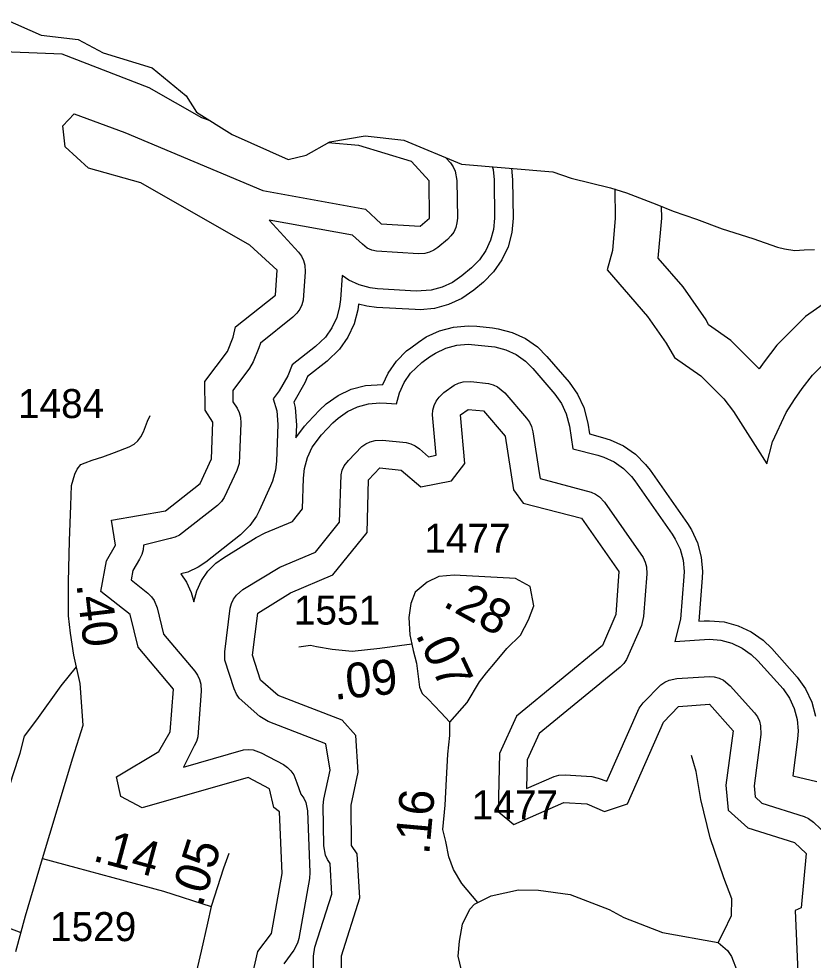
# Model space of a CAD drawing. Extents: x 2290615 to 2522933, y 819489 to 1012715.
# Drawn here: x 2339390 to 2342811, y 1000291 to 1004345 of the extents above; entities that cross this region are included whole.
import ezdxf

# ---------------------------------------------------------------- set-up
doc = ezdxf.new("R2010")
doc.units = 0
for name, color, linetype in [('Exist Boundary Political CountyLine', 7, 'Continuous'), ('Exist Hydrographic Buffer Line', 7, 'Continuous'), ('Exist Hydrographic Lake Shore', 7, 'Continuous'), ('Exist Road Non-System Type 51', 7, 'Continuous'), ('Exist Road Secondary Mileage Tenths English Label', 7, 'Continuous'), ('Exist Road Secondary Type 51 Attributed', 7, 'Continuous'), ('Exist Road Secondary Type 51 Number Label', 7, 'Continuous')]:
    doc.layers.add(name, color=color, linetype=linetype)

msp = doc.modelspace()

# ---------------------------------------------------------------- linework, layer by layer
at = {"layer": 'Exist Boundary Political CountyLine'}
msp.add_lwpolyline([(2339326.3, 1004344.5), (2339485.7, 1004274.3), (2339645.1, 1004255.2), (2339753.5, 1004197.8), (2339963.9, 1004134), (2340110.6, 1004012.7), (2340155.2, 1003942.5), (2340308.2, 1003846.8), (2340550.6, 1003738.4), (2340627.1, 1003757.5), (2340729.1, 1003814.9), (2340882.1, 1003840.4), (2341047.9, 1003821.3), (2341296.6, 1003719.2), (2341690.2, 1003686), (2341768.5, 1003659), (2341938.9, 1003616.8), (2342007.1, 1003595.6), (2342137.5, 1003545.2), (2342208, 1003516.3), (2342308.3, 1003481.3), (2342418.9, 1003440.6), (2342551.3, 1003398.5), (2342657.9, 1003361.5), (2342687.7, 1003353.9), (2342732, 1003346.5), (2342772, 1003349.1), (2342817.8, 1003351.7)], dxfattribs=at)
at = {"layer": 'Exist Hydrographic Buffer Line'}
for points in [[(2341227.3, 1003747.7), (2341248.8, 1003724.4), (2341260.9, 1003707.3), (2341269.7, 1003688.3), (2341276.9, 1003648.7), (2341278.9, 1003486.4), (2341277.1, 1003465.6), (2341271.6, 1003445.4), (2341263, 1003426.5), (2341250.9, 1003409.3), (2341236.1, 1003394.7), (2341195.1, 1003360), (2341177.9, 1003348), (2341158.8, 1003339.2), (2341138.7, 1003333.8), (2341111.2, 1003332.1), (2340930.2, 1003343.3), (2340909.9, 1003348.8), (2340890.8, 1003357.5), (2340869.5, 1003373.4), (2340827.2, 1003412.6), (2340468.8, 1003477.5), (2340594.9, 1003339.5), (2340606.8, 1003322.4), (2340615.6, 1003303.5), (2340621.1, 1003283.2), (2340622.6, 1003254.7)], [(2341429.3, 1003708), (2341432.5, 1003695.9), (2341436.8, 1003650.8), (2341438.9, 1003486.4), (2341434.6, 1003437.9), (2341421.9, 1003390.7), (2341401.4, 1003346.5), (2341373.5, 1003306.4), (2341339.2, 1003272.2), (2341297.8, 1003237.4), (2341257.8, 1003209.4), (2341213.5, 1003188.8), (2341166.4, 1003176.2), (2341102, 1003172.4), (2340934.9, 1003181.8), (2340902.5, 1003185.7), (2340855.1, 1003198.4), (2340810.8, 1003219), (2340781.9, 1003239.2), (2340775.3, 1003135.9), (2340771.6, 1003105.3), (2340758.9, 1003058.1), (2340738.4, 1003013.9), (2340710.3, 1002973.9), (2340668.3, 1002933.2), (2340566.8, 1002854), (2340547.9, 1002807.3), (2340511.6, 1002743.2), (2340485.2, 1002708.4), (2340501.6, 1002656.3), (2340505.7, 1002597), (2340499.7, 1002439.1), (2340495.6, 1002401.1), (2340482.9, 1002354), (2340474.3, 1002333.2), (2340425.3, 1002226.2)], [(2341512.3, 1003701), (2341516.8, 1003651.8), (2341518.9, 1003486.4), (2341513.3, 1003424), (2341497.1, 1003363.3), (2341470.7, 1003306.4), (2341434.6, 1003255), (2341390.7, 1003211.1), (2341349.5, 1003176.2)], [(2341957.4, 1003612.2), (2341958.9, 1003486.4), (2341946.6, 1003347.5), (2341924, 1003263.8), (2341997.4, 1003178.4), (2342097.7, 1003062.2), (2342177.7, 1002948), (2342214, 1002886.6), (2342328.2, 1002806.6), (2342426.6, 1002708.1), (2342468.9, 1002653.1), (2342611.2, 1002428.7), (2342636.2, 1002522.4), (2342695.2, 1002648.8), (2342731.1, 1002705.6), (2342764.1, 1002753.1), (2342808.2, 1002810.5), (2342906.6, 1002909)], [(2342579.2, 1002837.4), (2342456.6, 1002959.9), (2342360.6, 1003027), (2342351, 1003047.9), (2342250.9, 1003190.8), (2342143.7, 1003314.2), (2342158.8, 1003486.4), (2342158.3, 1003536.7)], [(2343389.7, 1003293.5), (2343247.2, 1003281.1), (2343078.9, 1003235.9), (2342920.8, 1003162.3), (2342778.1, 1003062.3), (2342654.8, 1002939.1), (2342599.9, 1002867.3), (2342579.2, 1002837.4)], [(2340622.6, 1003254.7), (2340614.2, 1003133), (2340608.6, 1003112.8), (2340599.8, 1003093.9), (2340587.9, 1003076.8), (2340569.9, 1003059.3), (2340430.2, 1002947.4), (2340424.1, 1002928), (2340399.7, 1002867.3), (2340384.1, 1002839.8), (2340311.1, 1002743.5), (2340311.7, 1002695.5), (2340330, 1002667.7), (2340338.6, 1002648.7), (2340344.1, 1002628.5), (2340346, 1002603.1), (2340338.2, 1002428.9), (2340328.9, 1002399.8), (2340274.8, 1002282.8), (2340262.9, 1002265.7), (2340245.5, 1002248.5), (2340081.9, 1002121.1), (2340063, 1002112.3), (2340041.9, 1002106.8), (2339926.8, 1002078.3), (2339925.2, 1002057.4), (2339919.7, 1002037.1), (2339910.2, 1002016.9), (2339881.1, 1001968.2), (2339873.9, 1001928.1), (2339946.1, 1001870.8), (2339960.9, 1001856), (2339973, 1001838.9), (2339985.5, 1001808.1), (2340013.6, 1001695.2), (2340147.9, 1001535.4), (2340160, 1001518.3), (2340168.6, 1001499.3), (2340174.1, 1001479.1), (2340175.8, 1001449.2), (2340160.2, 1001253), (2340154.6, 1001232.8), (2340145.6, 1001213.4), (2340098.7, 1001122.4), (2340357.2, 1001195.8), (2340377.9, 1001197.7), (2340398.7, 1001195.8), (2340434.1, 1001183.7), (2340529.9, 1001132.8), (2340547.1, 1001120.8), (2340561.9, 1001106)], [(2341349.5, 1003176.2), (2341297.8, 1003140.2), (2341241.2, 1003113.7), (2341180.3, 1003097.5), (2341118, 1003091.9), (2341097.5, 1003092.5), (2340930.4, 1003102), (2340888.3, 1003107), (2340853.5, 1003116.2), (2340850.4, 1003091.4), (2340834.2, 1003030.7), (2340807.7, 1002973.9), (2340771.6, 1002922.6), (2340717.7, 1002870.2), (2340632.8, 1002804.1), (2340622.2, 1002777.4), (2340574.2, 1002693.4), (2340580.3, 1002670.2), (2340585.7, 1002594), (2340583.6, 1002539.4), (2340620.1, 1002590.8), (2340635.7, 1002608.1), (2340684.7, 1002659.4), (2340713.4, 1002686.5), (2340764.9, 1002722.5), (2340821.7, 1002749.1), (2340882.4, 1002765.3), (2340957.6, 1002770.1), (2340980.2, 1002818.5), (2341016.1, 1002869.9), (2341060.4, 1002914.3), (2341078.4, 1002928.3), (2341111.4, 1002952.6), (2341144.8, 1002974.5), (2341201.6, 1003001.1), (2341262.3, 1003017.3), (2341324.9, 1003022.7), (2341362.6, 1003020.8), (2341429.7, 1003013.7), (2341454.5, 1003010.2), (2341515.2, 1002994), (2341572, 1002967.5), (2341623.4, 1002931.5), (2341664.4, 1002891), (2341760.6, 1002779.3), (2341796.7, 1002728), (2341823.2, 1002671.1), (2341840.6, 1002603.3), (2341848, 1002556.8), (2341904.4, 1002542.2), (2341937.2, 1002532), (2341994, 1002505.5), (2342045.4, 1002469.5), (2342089.7, 1002425.1), (2342108.6, 1002400.5), (2342269.8, 1002170.9), (2342286.6, 1002144.2), (2342313.2, 1002087.4), (2342329.4, 1002026.7), (2342335, 1001964.2), (2342333.9, 1001937), (2342319.4, 1001750.4), (2342341.5, 1001751.8), (2342364.9, 1001752.5), (2342427.4, 1001747.1), (2342488.1, 1001730.9), (2342544.9, 1001704.3), (2342596.4, 1001668.4), (2342633.1, 1001632.7), (2342742.6, 1001510), (2342778.7, 1001458.6), (2342805.1, 1001401.7), (2342821.3, 1001341.1)], [(2340425.3, 1002226.2), (2340413.4, 1002202.7), (2340385.3, 1002162.7), (2340344.3, 1002123), (2340195.5, 1002005.3), (2340161.8, 1001982.6), (2340117.7, 1001961.9), (2340087, 1001953.8), (2340111.4, 1001918.8), (2340131.9, 1001874.6), (2340143.2, 1001833.8), (2340155.9, 1001880.9), (2340176.4, 1001925.2), (2340204.5, 1001965.2), (2340238.9, 1001999.7), (2340270.9, 1002022.9), (2340412, 1002110.7), (2340451.4, 1002131.2), (2340568.4, 1002180.2), (2340612.3, 1002234.9), (2340615.8, 1002366.9), (2340620.1, 1002408.1), (2340632.8, 1002455.2), (2340653.3, 1002499.4), (2340693.3, 1002552.8), (2340742.3, 1002604.1), (2340764.9, 1002625.2), (2340804.9, 1002653.2), (2340849.2, 1002673.9), (2340896.3, 1002686.5), (2340944.9, 1002690.7), (2340973.2, 1002689.3), (2341016.1, 1002687.1), (2341029, 1002734.2), (2341049.5, 1002778.4), (2341077.4, 1002818.5), (2341126, 1002863.9), (2341159, 1002888.2), (2341184.8, 1002905.2), (2341229.1, 1002925.9), (2341276.5, 1002938.5), (2341324.9, 1002942.8), (2341354.2, 1002941.2), (2341440.3, 1002931.5), (2341487.7, 1002918.9), (2341532, 1002898.3), (2341572, 1002870.2), (2341604, 1002838.7), (2341699.3, 1002728), (2341727.4, 1002688), (2341747.9, 1002643.7), (2341761.6, 1002591), (2341776.8, 1002492.7), (2341884.5, 1002464.8), (2341909.7, 1002456.9), (2341954, 1002436.3), (2341994, 1002408.3), (2342028.4, 1002373.7), (2342043.2, 1002354.6), (2342204.1, 1002125), (2342217.5, 1002104.2), (2342238, 1002060), (2342250.7, 1002012.8), (2342255, 1001964.2), (2342254.2, 1001943), (2342240.2, 1001758.5), (2342215.6, 1001663.4), (2342364.9, 1001672.6), (2342413.5, 1001668.4), (2342460.7, 1001655.7), (2342505, 1001635), (2342544.9, 1001607), (2342573.6, 1001579.3), (2342681.5, 1001458.6), (2342709.4, 1001418.6), (2342729.9, 1001374.3), (2342742.6, 1001327.1), (2342746.9, 1001278.6), (2342744.5, 1001241.8), (2342723.7, 1001084.7), (2342826.7, 1001060.2)], [(2340738, 1000574.4), (2340730.2, 1000707.6), (2340718.9, 1000724.2), (2340710.1, 1000743.1), (2340703, 1000782.8), (2340700.9, 1000956.5), (2340703.8, 1000983.4), (2340731.3, 1001109.6), (2340712.4, 1001222.8), (2340463.7, 1001318.9), (2340428.4, 1001340.2), (2340339, 1001419.5), (2340326.9, 1001436.6), (2340316.8, 1001459.4), (2340277.7, 1001582.8), (2340276.9, 1001618.7), (2340300.6, 1001805.9), (2340306.2, 1001826.2), (2340315, 1001845.2), (2340326.9, 1001862.3), (2340355.4, 1001887), (2340513.5, 1001983.5), (2340667.7, 1002048.3), (2340770.8, 1002176.5), (2340777.6, 1002380.3), (2340783.1, 1002400.5), (2340791.9, 1002419.5), (2340809.2, 1002442.3), (2340867.6, 1002502.7), (2340884.8, 1002514.7), (2340903.9, 1002523.5), (2340924.2, 1002529), (2340956.8, 1002530.1), (2341057.7, 1002519.6), (2341078, 1002514.2), (2341096.9, 1002505.4), (2341115.1, 1002492.5), (2341155.1, 1002458), (2341187.1, 1002464.9), (2341171.9, 1002638.5), (2341173.5, 1002659.3), (2341179.1, 1002679.5), (2341187.9, 1002698.4), (2341199.8, 1002715.6), (2341220.7, 1002735), (2341264.8, 1002766.7), (2341283.9, 1002775.5), (2341304.2, 1002781), (2341337.4, 1002782.1), (2341412.6, 1002773.9), (2341432.9, 1002768.5), (2341451.8, 1002759.6), (2341482.6, 1002734.1), (2341576.9, 1002625.1), (2341589, 1002608), (2341597.6, 1002589), (2341603.3, 1002566.4), (2341630.8, 1002389.2), (2341634.9, 1002364.4), (2341854.9, 1002306.5), (2341874, 1002297.7), (2341891.2, 1002285.7), (2341912.1, 1002262.6), (2342078.9, 1002024.2), (2342087.7, 1002005.3), (2342093.2, 1001985.1), (2342094.6, 1001955.1), (2342080.7, 1001770.7), (2342071.5, 1001732.6), (2342007.9, 1001585.9), (2341996, 1001568.8), (2341980, 1001553.1), (2341630.6, 1001266.8), (2341579.3, 1001153.9), (2341576.5, 1001030), (2341696, 1001082.2), (2341716.1, 1001087.6), (2341743.6, 1001089.3), (2341857.6, 1001081.9), (2341884.7, 1001073.8), (2341923.2, 1001061), (2342061.8, 1001375.4), (2342079.5, 1001398.7), (2342154.7, 1001475.8), (2342171.9, 1001487.8), (2342191, 1001496.6), (2342224.2, 1001503.6), (2342364.9, 1001512.6), (2342385.6, 1001510.8), (2342405.9, 1001505.3), (2342425, 1001496.5), (2342454.5, 1001472.5), (2342558.9, 1001355.6), (2342571, 1001338.5), (2342579.6, 1001319.7), (2342585.1, 1001299.4), (2342585.9, 1001262.9), (2342556.6, 1001041.9), (2342561.1, 1000994.1), (2342590.9, 1000967.5)], [(2340561.9, 1001106), (2340574, 1001088.9), (2340587.1, 1001054.8), (2340604.9, 1001005.9), (2340616.8, 1000988.8), (2340625.7, 1000969.9), (2340633, 1000933.8), (2340643.9, 1000668.3), (2340642.3, 1000642.4), (2340596.1, 1000384.3), (2340590.8, 1000364.3), (2340574.2, 1000333.7), (2340530.9, 1000275.6)], [(2342590.9, 1000967.5), (2342771.9, 1000909.9), (2342791, 1000901), (2342813.1, 1000884.3), (2342873, 1000827), (2342884.9, 1000809.9), (2342893.7, 1000790.9), (2342911.2, 1000768)], [(2340535.4, 999640), (2340585.9, 999676), (2340604.9, 999684.8), (2340642.9, 999692), (2340755.2, 999694.6), (2340773.7, 999849.2), (2340784.2, 999885.4), (2340848.7, 1000038.8), (2340793.2, 1000048.3), (2340772.9, 1000053.8), (2340754, 1000062.6), (2340732.5, 1000078.4), (2340688, 1000120.8), (2340675.9, 1000137.9), (2340667.3, 1000156.8), (2340659.9, 1000196.8), (2340658.9, 1000308.4), (2340664.6, 1000346.2), (2340738, 1000574.4)]]:
    msp.add_lwpolyline(points, dxfattribs=at)
at = {"layer": 'Exist Hydrographic Lake Shore'}
for points in [[(2340211.6, 1003907.3), (2340178.8, 1003918.8), (2339951.8, 1004047.3), (2339575.8, 1004192.8), (2339250.8, 1004205.5), (2338975.8, 1004167.9), (2338868.8, 1004068.3), (2338861.8, 1003933.5), (2338971.9, 1003852.7), (2338963.9, 1003770.2), (2338898.9, 1003691.9), (2338915.9, 1003627.2), (2339007.8, 1003561.9), (2339009.8, 1003453.6), (2339118.9, 1003405.7), (2339120, 1003244.9), (2339254.9, 1003132.2), (2339229.9, 1002947.5)], [(2340312.9, 1002972.9), (2340322.8, 1003018.7), (2340495.9, 1003153.9), (2340502.8, 1003262.4), (2340384.9, 1003369.3), (2339916, 1003638.8), (2339689.8, 1003701.7), (2339588.9, 1003792.7), (2339578.9, 1003884.2), (2339628.9, 1003935.4), (2339845.8, 1003855.7), (2340440.9, 1003604.6), (2340882.8, 1003524.4), (2340950.9, 1003461.4), (2341118, 1003452), (2341158.8, 1003486.4), (2341156.9, 1003647.3), (2341080.9, 1003729.4), (2340854.9, 1003798.9), (2340720.9, 1003810.3)], [(2340396, 1000228.2), (2340420, 1000327.6), (2340478, 1000405.4), (2340523.9, 1000663.4), (2340512.9, 1000928.8), (2340487.9, 1000947.5), (2340470, 1001028.9), (2340377.9, 1001077.7), (2339920.9, 1000947.2), (2339829, 1000995.9), (2339811, 1001080.4), (2339992.9, 1001189.8), (2340041.9, 1001273.8), (2340056, 1001458.3), (2339903.9, 1001639.1), (2339869, 1001778.9), (2339742.9, 1001878.6), (2339766.9, 1002010.9), (2339806.9, 1002078.3), (2339788.8, 1002185.9), (2340022, 1002225.1), (2340170.8, 1002342.8), (2340219.9, 1002449.7), (2340225.8, 1002607.7), (2340192, 1002658.8), (2340190.9, 1002783.4), (2340288.3, 1002912.3), (2340312.9, 1002972.9)], [(2340779.8, 1000197.9), (2340779, 1000309.6), (2340859, 1000559), (2340847.9, 1000749), (2340822.9, 1000784.2), (2340820.9, 1000958), (2340852, 1001100.5), (2340842, 1001257.6), (2340782.9, 1001324.2), (2340506.9, 1001430.9), (2340430.9, 1001496.7), (2340396, 1001603.7), (2340419, 1001785.1), (2340559.8, 1001872.9), (2340741.9, 1001949.4), (2340890, 1002132.8), (2340895.9, 1002359.5), (2340944.9, 1002410.7), (2341037, 1002401.4), (2341120.9, 1002329.3), (2341253.9, 1002354.6), (2341310.9, 1002429.2), (2341291.9, 1002638.5), (2341324.9, 1002662.8), (2341391.9, 1002655.7), (2341484.8, 1002547.9), (2341520.9, 1002316.4), (2341562.9, 1002258.9), (2341813.9, 1002193.8), (2341974.9, 1001964.2), (2341960.9, 1001779.7), (2341903.9, 1001645.9), (2341533, 1001341.9), (2341460, 1001181.3), (2341453.9, 1000931.6), (2341521.9, 1000875.2), (2341737, 1000969.4), (2341836.9, 1000963.8), (2341913, 1000930.8), (2342012, 1000964.4), (2342166, 1001315.5), (2342232, 1001383.8), (2342364.9, 1001392.6), (2342467, 1001278.6), (2342435.8, 1001044.3), (2342445.9, 1000936.2), (2342530, 1000861), (2342730.9, 1000797.1), (2342781, 1000749.9), (2342759, 1000516), (2342734, 1000505.1), (2342745.9, 1000239.7)]]:
    msp.add_lwpolyline(points, dxfattribs=at)
at = {"layer": 'Exist Road Non-System Type 51'}
for points in [[(2339252.6, 1000464), (2339217.9, 1000503.4), (2339214.8, 1000539), (2339219.5, 1000582.4), (2339228.8, 1000627.4), (2339250.5, 1000689.4), (2339310.9, 1000900.3), (2339329.5, 1000973.2), (2339363.6, 1001086.4), (2339395.8, 1001182.6), (2339414.4, 1001255.5), (2339467.1, 1001325.3), (2339572.5, 1001472.6), (2339638.1, 1001553.3)], [(2342402.5, 1000366.2), (2342426.8, 1000413.6), (2342459.4, 1000483.4), (2342460.9, 1000554.7), (2342426.8, 1000644.6), (2342367.9, 1000816.8), (2342327.6, 1000982.7), (2342307.5, 1001103.6), (2342287.3, 1001171.9)], [(2339399.3, 1000408), (2339252.6, 1000464), (2339193, 1000482.6), (2339120.9, 1000505.1), (2339039.5, 1000533), (2338953, 1000546.5), (2338867, 1000555.6), (2338796.9, 1000566.7), (2338752.7, 1000580.1), (2338712.5, 1000593.7), (2338692.3, 1000613.5)]]:
    msp.add_lwpolyline(points, dxfattribs=at)
at = {"layer": 'Exist Road Secondary Type 51 Attributed'}
for points in [[(2339492.3, 1000729), (2339622.1, 1001162.1), (2339667, 1001303.2), (2339654.5, 1001482.1), (2339626.2, 1001604.5), (2339612.9, 1001698.4), (2339604, 1001774.2), (2339604.4, 1001920.1), (2339608.2, 1002096.2), (2339614.3, 1002248.1), (2339617.4, 1002334.3), (2339630.7, 1002384.3), (2339640.5, 1002404.5), (2339656.3, 1002424.6), (2339676.1, 1002433), (2339705.9, 1002443.2), (2339751.8, 1002457.7), (2339801.6, 1002476.4), (2339865.2, 1002501.2), (2339887.1, 1002513.5), (2339903, 1002527.6), (2339914.7, 1002543.7), (2339926.4, 1002566), (2339943.9, 1002612.1), (2339955.7, 1002636.2)], [(2341592.2, 1001899.2), (2341528.7, 1001934.3), (2341265.3, 1001948.3), (2341198.6, 1001943.6), (2341149.1, 1001918.8), (2341096.4, 1001875.4), (2341077.8, 1001827.3), (2341070, 1001766.8), (2341074.7, 1001692.4), (2341083, 1001651.6)], [(2341246.7, 1001315.6), (2341321.1, 1001400.9), (2341373.8, 1001489.2), (2341404.7, 1001528), (2341443.5, 1001574.5), (2341491.5, 1001633.5), (2341550.4, 1001690.8), (2341584.5, 1001756), (2341607.7, 1001816.4), (2341592.2, 1001899.2)], [(2341083, 1001651.6), (2340945.1, 1001632.9), (2340825.8, 1001620.5), (2340739, 1001628.2), (2340672.4, 1001640.6), (2340646, 1001645.3), (2340596.4, 1001639.1)], [(2341083, 1001651.6), (2341088.6, 1001624.2), (2341102.6, 1001569.9), (2341110.3, 1001512.5), (2341115, 1001466), (2341127.4, 1001439.6), (2341153.7, 1001414.8), (2341207.9, 1001357.4), (2341246.7, 1001315.6)], [(2341367.2, 1000538.8), (2341298.7, 1000621), (2341261.5, 1000681.5), (2341241.4, 1000735.8), (2341229, 1000802.4), (2341216.6, 1000853.6), (2341225.9, 1000957.5), (2341232.1, 1001070.7), (2341238.3, 1001177.7), (2341246, 1001258.4), (2341246.7, 1001315.6)], [(2340294.3, 1000750.7), (2340271, 1000686.5), (2340218.2, 1000521.4)], [(2339377.3, 1000327.4), (2339419.2, 1000480.9), (2339492.3, 1000729)], [(2339492.3, 1000729), (2339635.2, 1000689.5), (2339794.9, 1000646.1), (2340013.4, 1000587.2), (2340218.2, 1000521.4)], [(2341367.2, 1000538.8), (2341423.8, 1000567.5), (2341541.5, 1000593.9), (2341628.3, 1000592.3), (2341764.7, 1000573.7), (2341932, 1000508.6), (2341995.6, 1000474.5), (2342162.9, 1000409.3), (2342402.5, 1000366.2), (2342442.7, 1000332.6), (2342459.2, 1000306.9), (2342483.8, 1000243.1)], [(2341550, 998913.4), (2341543.8, 999082.7), (2341543.8, 999273.4), (2341526.7, 999388.2), (2341480.2, 999484.3), (2341384.3, 999585.9), (2341330, 999643.3), (2341300.6, 999692.9), (2341282, 999747.1), (2341291.3, 999838.6), (2341314.5, 999936.3), (2341340.9, 1000011.6), (2341356.3, 1000080.8), (2341350.2, 1000117), (2341334.6, 1000159.9), (2341302, 1000223.4), (2341281.9, 1000307.2), (2341288.1, 1000372.3), (2341300.5, 1000445.2), (2341333, 1000510.3), (2341352.7, 1000531.5), (2341367.2, 1000538.8)], [(2340218.2, 1000521.4), (2340201.9, 1000449.7), (2340175.4, 1000329.3), (2340148.7, 1000219), (2340138.1, 1000098.9), (2340135.6, 999978.9), (2340134.8, 999881)]]:
    msp.add_lwpolyline(points, dxfattribs=at)

# ---------------------------------------------------------------- texts
at = {"layer": 'Exist Road Secondary Mileage Tenths English Label'}
for s, rotation, p in [('.40', 276.7103, (2339637.6, 1001909.6)), ('.28', 331.0962, (2341211.7, 1001817.7)), ('.07', 295.1855, (2341097.4, 1001693.4)), ('.09', 5.9356, (2340749.6, 1001411.4)), ('.16', 84.8861, (2341157.2, 1000742)), ('.14', 344.907, (2339703.3, 1000720.2)), ('.05', 72.2819, (2340178.7, 1000516.4))]:
    msp.add_text(s, height=150, rotation=rotation, dxfattribs=at).set_placement(p)
at = {"layer": 'Exist Road Secondary Type 51 Number Label'}
for s, p in [('1484', (2339386, 1002625.1)), ('1477', (2341136.3, 1002045)), ('1551', (2340574.3, 1001735.7)), ('1477', (2341340.8, 1000896.9)), ('1529', (2339524.2, 1000372.6))]:
    msp.add_text(s, height=125, dxfattribs=at).set_placement(p)

doc.saveas('drawing.dxf')
